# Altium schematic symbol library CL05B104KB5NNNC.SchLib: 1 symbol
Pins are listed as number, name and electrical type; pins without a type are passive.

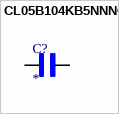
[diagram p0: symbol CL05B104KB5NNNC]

## CL05B104KB5NNNC
designator C?
0.1 ÂµF Â±10% 50V Ceramic Capacitor X7R 0402 (1005 Metric); MF: Samsung Electro-Mechanics; MP: CL05B104KB5NNNC
footprint CAPC1005X55N
pins: 1, 2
